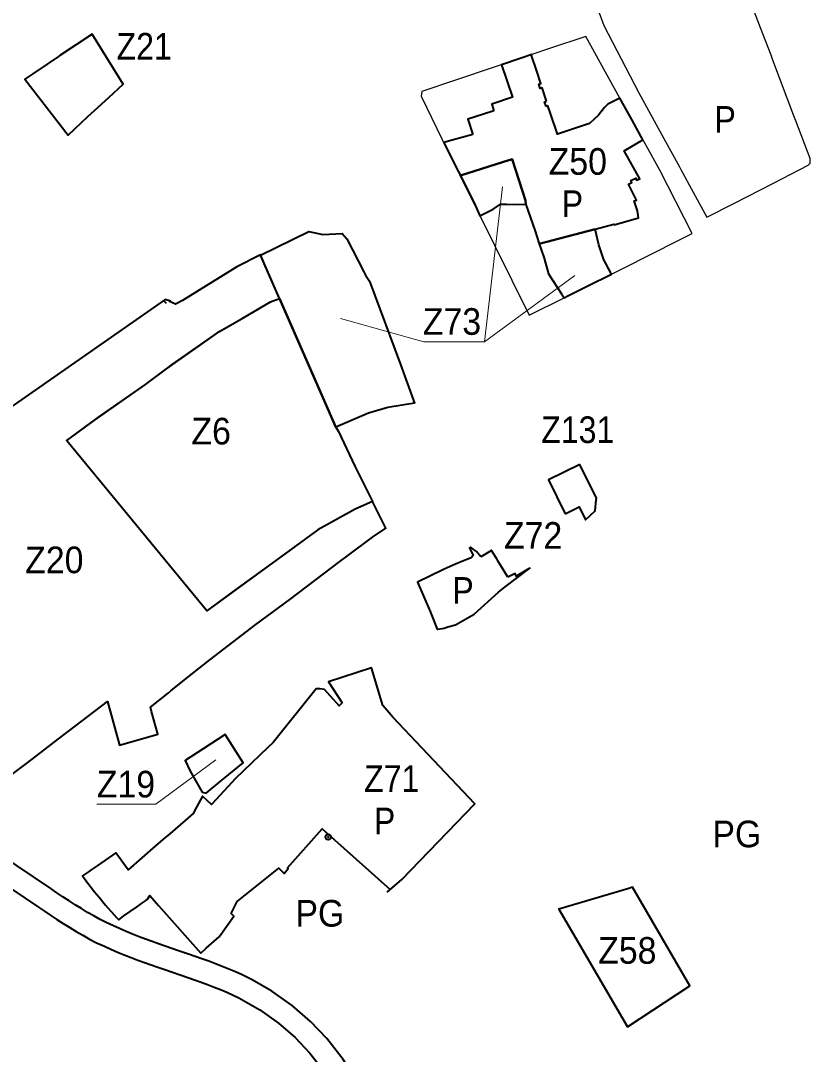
# Model space of a CAD drawing. Extents: x -650276 to -642489, y -1074311 to -1066658.
# Drawn here: x -648043 to -647332, y -1071620 to -1070690 of the extents above; entities that cross this region are included whole.
import ezdxf

# ---------------------------------------------------------------- set-up
doc = ezdxf.new("R2010")
doc.units = 0
doc.header["$LTSCALE"] = 9.6
doc.header["$PDMODE"] = 32
doc.header["$PDSIZE"] = 4.8
for name, color, linetype, lineweight in [('42', 7, 'Continuous', 25), ('44', 7, 'Continuous', 40), ('45', 7, 'Continuous', 40), ('46', 7, 'Continuous', 13), ('60', 7, 'Continuous', 35)]:
    doc.layers.add(name, color=color, linetype=linetype, lineweight=lineweight)

msp = doc.modelspace()

# ---------------------------------------------------------------- linework, layer by layer
at = {"layer": '42'}
for points in [[(-647523.27, -1070680.11), (-647518.19, -1070693.93), (-647502.59, -1070724.13), (-647486.84, -1070754.54), (-647464.3, -1070795.6), (-647450.23, -1070821.25), (-647448.84, -1070823.79), (-647437.79, -1070844.12), (-647425.58, -1070866.7), (-647401.15, -1070854.25), (-647365.48, -1070835.85), (-647334.27, -1070819.86), (-647332.51, -1070817.97), (-647332.25, -1070813.72), (-647345.18, -1070779.89), (-647346.96, -1070775.41), (-647365.94, -1070725.08), (-647367.67, -1070720.73), (-647377.04, -1070696.22), (-647386.39, -1070671.74)], [(-647717.363, -1071306.29), (-647727.368, -1071272.362), (-647766.35, -1071285.11), (-647753.89, -1071303.94), (-647756.67, -1071306.77), (-647769.85, -1071291.91), (-647774.14, -1071291.34), (-647777.4, -1071291.32), (-647815.95, -1071339.71), (-647820.93, -1071344.25), (-647849.86, -1071372.18), (-647867.45, -1071390.95), (-647871.68, -1071395.59), (-647879.76, -1071387.96), (-647885.05, -1071397.88), (-647888.11, -1071403.61), (-647895.29, -1071409.81), (-647904.3, -1071417.58), (-647911.04, -1071423.39), (-647913.31, -1071425.35), (-647921.96, -1071432.81), (-647946.78, -1071454.23), (-647957.906, -1071439.06), (-647974.66, -1071450.62), (-647977.28, -1071452.43), (-647979.88, -1071454.22), (-647982.46, -1071456), (-647985.06, -1071457.79), (-647987.8, -1071459.68), (-647984, -1071465), (-647977.13, -1071474.05), (-647972.76, -1071479)], [(-647710.546, -1071472.023), (-647700.078, -1071462.96), (-647634.524, -1071394.901), (-647708.429, -1071316.821), (-647717.363, -1071306.29)], [(-647803.1, -1071452.66), (-647771.82, -1071417.42), (-647710.546, -1071472.023)], [(-647848.4, -1071482.78), (-647810.97, -1071452.92), (-647806.15, -1071457.48)], [(-647806.15, -1071457.48), (-647802.53, -1071453.19), (-647803.1, -1071452.66)], [(-647972.76, -1071479), (-647967.13, -1071486.01), (-647957.07, -1071497.13), (-647955.14, -1071499.23), (-647950.56, -1071495.85), (-647944.81, -1071491.78), (-647939.31, -1071487.88), (-647933.88, -1071484.04), (-647931.17, -1071482.12), (-647929.26, -1071480.77), (-647927.2, -1071477.54), (-647919.22, -1071486.5), (-647881.16, -1071529.25)], [(-647881.16, -1071529.25), (-647876.27, -1071524.96), (-647864.69, -1071514.65), (-647851.45, -1071495.96), (-647853.77, -1071493.78), (-647848.4, -1071482.78)]]:
    msp.add_lwpolyline(points, dxfattribs=at)
msp.add_lwpolyline([(-647534.33, -1070703.84), (-647567.08, -1070714.8), (-647583.22, -1070720.2), (-647651.82, -1070743.17), (-647682.08, -1070753.29), (-647682.67, -1070757.67), (-647663.71, -1070796.77), (-647585.55, -1070954.94), (-647553.94, -1070939.11), (-647532.58, -1070928.392), (-647511.37, -1070917.79), (-647501.26, -1070912.72), (-647450.8, -1070887.42), (-647438.82, -1070881.43), (-647467.89, -1070824.15), (-647480.13, -1070802.09), (-647503.76, -1070759.31)], close=True, dxfattribs=at)
at = {"layer": '44'}
for points in [[(-647834.953, -1071553.406), (-647837.929, -1071551.872), (-647843.891, -1071549), (-647849.898, -1071546.282), (-647855.937, -1071543.707), (-647861.998, -1071541.254), (-647868.073, -1071538.911), (-647874.155, -1071536.658), (-647880.233, -1071534.48), (-647886.305, -1071532.36), (-647892.363, -1071530.282), (-647901.28, -1071527.249), (-647907.294, -1071525.204), (-647913.282, -1071523.152), (-647919.238, -1071521.081), (-647925.157, -1071518.976), (-647931.035, -1071516.824), (-647936.866, -1071514.613), (-647942.644, -1071512.329), (-647948.363, -1071509.96), (-647954.016, -1071507.496), (-647959.792, -1071504.833), (-647966.547, -1071501.883), (-647972.035, -1071499.009), (-647977.67, -1071495.885), (-647983.266, -1071492.628), (-647988.829, -1071489.259), (-647994.366, -1071485.79), (-647999.887, -1071482.241), (-648005.399, -1071478.627), (-648010.917, -1071474.963), (-648016.446, -1071471.268), (-648063.593, -1071439.723)], [(-648074.86, -1071456.248), (-648027.562, -1071487.894), (-648022.005, -1071491.607), (-648016.415, -1071495.321), (-648010.777, -1071499.017), (-648005.082, -1071502.678), (-647999.319, -1071506.287), (-647993.478, -1071509.826), (-647987.55, -1071513.275), (-647981.525, -1071516.615), (-647975.201, -1071519.929), (-647967.982, -1071523.081), (-647962.2, -1071525.746), (-647956.187, -1071528.368), (-647950.146, -1071530.869), (-647944.088, -1071533.263), (-647938.019, -1071535.566), (-647931.945, -1071537.788), (-647925.874, -1071539.949), (-647919.808, -1071542.058), (-647913.756, -1071544.132), (-647907.72, -1071546.185), (-647898.827, -1071549.208), (-647892.847, -1071551.26), (-647886.903, -1071553.336), (-647881.001, -1071555.45), (-647875.147, -1071557.619), (-647869.348, -1071559.856), (-647863.611, -1071562.177), (-647857.944, -1071564.594), (-647847.103, -1071569.497)], [(-647725.629, -1071678.373), (-647735.352, -1071657.117), (-647741.34, -1071644.028), (-647753.065, -1071625.201), (-647767.784, -1071606.225), (-647782.408, -1071590.847), (-647798.911, -1071576.526), (-647817.375, -1071563.458), (-647834.953, -1071553.406)], [(-647847.103, -1071569.497), (-647828.141, -1071580.34), (-647811.272, -1071592.28), (-647796.24, -1071605.324), (-647782.97, -1071619.278)], [(-647782.97, -1071619.278), (-647769.498, -1071636.647), (-647758.994, -1071653.513), (-647743.48, -1071687.426), (-647611.514, -1071974.086)]]:
    msp.add_lwpolyline(points, dxfattribs=at)
at = {"layer": '45'}
for p, q in [((-647914.73, -1070941.682), (-647912.347, -1070944.065)), ((-647914.73, -1070941.682), (-647912.347, -1070944.065)), ((-647713.442, -1071474.53), (-647700.078, -1071462.96)), ((-647713.442, -1071474.53), (-647700.078, -1071462.96))]:
    msp.add_line(p, q, dxfattribs=at)
for points in [[(-648032.601, -1070737.472), (-648039.82, -1070742.33), (-648000.85, -1070792.88), (-647994.63, -1070787.05), (-647982.89, -1070776.05), (-647976.97, -1070770.51), (-647964.21, -1070758.77), (-647951.11, -1070746.78), (-647979.17, -1070701.65), (-648008.28, -1070720.96), (-648009.29, -1070721.79), (-648019.49, -1070728.65)], [(-647827.363, -1070900.725), (-647783.95, -1070879.58), (-647771.47, -1070882.27), (-647753.81, -1070881.3), (-647749.75, -1070886.1), (-647734.48, -1070915.94), (-647732.97, -1070918.87), (-647729.27, -1070924.35), (-647701.45, -1070999.4), (-647688.9, -1071034.18), (-647712.74, -1071037.99), (-647730.17, -1071043.21), (-647759.52, -1071055.67)], [(-647827.363, -1070900.725), (-647783.95, -1070879.58), (-647771.47, -1070882.27), (-647753.81, -1070881.3), (-647749.75, -1070886.1), (-647734.48, -1070915.94), (-647732.97, -1070918.87), (-647729.27, -1070924.35), (-647701.45, -1070999.4), (-647688.9, -1071034.18), (-647712.74, -1071037.99), (-647730.17, -1071043.21), (-647759.52, -1071055.67)], [(-648001.766, -1071068.02), (-648001.922, -1071067.83), (-647973.304, -1071046.814), (-647930.96, -1071017.383), (-647912.11, -1071003.11), (-647906.9, -1070999.39), (-647875.248, -1070977.173), (-647864.03, -1070969.3), (-647843.928, -1070957.692), (-647818.33, -1070942.91), (-647810.243, -1070939.825), (-647759.52, -1071055.67), (-647757.19, -1071059.66), (-647742.64, -1071090.72), (-647726.74, -1071122.48), (-647742.35, -1071129.43), (-647775.982, -1071148.001), (-647775.982, -1071148.001), (-647875.939, -1071221.104)], [(-647974.66, -1071450.62), (-647977.28, -1071452.43), (-647979.88, -1071454.22), (-647982.46, -1071456), (-647985.06, -1071457.79), (-647987.8, -1071459.68), (-647984, -1071465), (-647977.13, -1071474.05), (-647972.76, -1071479), (-647967.13, -1071486.01), (-647957.07, -1071497.13), (-647955.14, -1071499.23), (-647950.56, -1071495.85), (-647944.81, -1071491.78), (-647939.31, -1071487.88), (-647933.88, -1071484.04), (-647931.17, -1071482.12), (-647929.26, -1071480.77), (-647927.2, -1071477.54), (-647919.22, -1071486.5), (-647881.16, -1071529.25), (-647876.27, -1071524.96), (-647864.69, -1071514.65), (-647851.45, -1071495.96), (-647853.77, -1071493.78), (-647848.4, -1071482.78), (-647810.97, -1071452.92), (-647806.15, -1071457.48), (-647802.53, -1071453.19), (-647803.1, -1071452.66), (-647771.82, -1071417.42), (-647710.546, -1071472.023), (-647700.078, -1071462.96), (-647634.524, -1071394.901), (-647708.429, -1071316.821), (-647717.363, -1071306.29), (-647727.368, -1071272.362), (-647766.35, -1071285.11), (-647753.89, -1071303.94), (-647756.67, -1071306.77), (-647769.85, -1071291.91), (-647774.14, -1071291.34), (-647777.4, -1071291.32), (-647815.95, -1071339.71), (-647820.93, -1071344.25), (-647849.86, -1071372.18), (-647867.45, -1071390.95), (-647871.68, -1071395.59), (-647879.76, -1071387.96), (-647885.05, -1071397.88), (-647888.11, -1071403.61), (-647895.29, -1071409.81), (-647904.3, -1071417.58), (-647911.04, -1071423.39), (-647913.31, -1071425.35), (-647921.96, -1071432.81), (-647946.78, -1071454.23), (-647957.906, -1071439.06)], [(-647974.66, -1071450.62), (-647977.28, -1071452.43), (-647979.88, -1071454.22), (-647982.46, -1071456), (-647985.06, -1071457.79), (-647987.8, -1071459.68), (-647984, -1071465), (-647977.13, -1071474.05), (-647972.76, -1071479), (-647967.13, -1071486.01), (-647957.07, -1071497.13), (-647955.14, -1071499.23), (-647950.56, -1071495.85), (-647944.81, -1071491.78), (-647939.31, -1071487.88), (-647933.88, -1071484.04), (-647931.17, -1071482.12), (-647929.26, -1071480.77), (-647927.2, -1071477.54), (-647919.22, -1071486.5), (-647881.16, -1071529.25), (-647876.27, -1071524.96), (-647864.69, -1071514.65), (-647851.45, -1071495.96), (-647853.77, -1071493.78), (-647848.4, -1071482.78), (-647810.97, -1071452.92), (-647806.15, -1071457.48), (-647802.53, -1071453.19), (-647803.1, -1071452.66), (-647771.82, -1071417.42), (-647710.546, -1071472.023), (-647700.078, -1071462.96), (-647634.524, -1071394.901), (-647708.429, -1071316.821), (-647717.363, -1071306.29), (-647727.368, -1071272.362), (-647766.35, -1071285.11), (-647753.89, -1071303.94), (-647756.67, -1071306.77), (-647769.85, -1071291.91), (-647774.14, -1071291.34), (-647777.4, -1071291.32), (-647815.95, -1071339.71), (-647820.93, -1071344.25), (-647849.86, -1071372.18), (-647867.45, -1071390.95), (-647871.68, -1071395.59), (-647879.76, -1071387.96), (-647885.05, -1071397.88), (-647888.11, -1071403.61), (-647895.29, -1071409.81), (-647904.3, -1071417.58), (-647911.04, -1071423.39), (-647913.31, -1071425.35), (-647921.96, -1071432.81), (-647946.78, -1071454.23), (-647957.906, -1071439.06)], [(-647879.09, -1071345.3), (-647895.37, -1071355.96), (-647890.7, -1071365.52), (-647880.14, -1071384.32), (-647876.34, -1071385.2), (-647862.25, -1071373.55), (-647859.44, -1071371.23), (-647843.23, -1071357.82), (-647859.31, -1071332.34)], [(-647879.09, -1071345.3), (-647895.37, -1071355.96), (-647890.7, -1071365.52), (-647880.14, -1071384.32), (-647876.34, -1071385.2), (-647862.25, -1071373.55), (-647859.44, -1071371.23), (-647843.23, -1071357.82), (-647859.31, -1071332.34)], [(-647497.04, -1071595.66), (-647440.67, -1071558.93), (-647492.3, -1071470), (-647495.85, -1071471.06), (-647558.654, -1071489.738)], [(-647497.04, -1071595.66), (-647440.67, -1071558.93), (-647492.3, -1071470), (-647495.85, -1071471.06), (-647558.654, -1071489.738)]]:
    msp.add_lwpolyline(points, close=True, dxfattribs=at)
for points in [[(-647569.92, -1070762.24), (-647573.88, -1070750.25), (-647575.58, -1070750.83), (-647576.81, -1070746.86), (-647575.09, -1070746.33), (-647578.79, -1070734.33), (-647583.38, -1070720.9), (-647583.22, -1070720.2), (-647593.6, -1070723.68), (-647610.33, -1070729.28), (-647600.53, -1070758.65), (-647619.2, -1070764.85), (-647617.36, -1070770.69)], [(-647636.12, -1070792.13), (-647654.89, -1070797.23), (-647662.26, -1070799.23), (-647650.908, -1070822.34), (-647647.405, -1070829.08), (-647609.58, -1070817.06), (-647600.8, -1070814.27), (-647588.89, -1070851.67), (-647588.4, -1070855.25), (-647584.6, -1070866.3), (-647580.22, -1070879.3), (-647578.703, -1070883.851), (-647578.703, -1070883.851), (-647576.469, -1070890.564), (-647526.13, -1070877.41), (-647509.1, -1070872.96), (-647508.96, -1070873.41), (-647487.16, -1070867.32), (-647487.91, -1070860.91), (-647490.92, -1070851.82), (-647488.8, -1070851.12), (-647494.1, -1070840.58), (-647495.93, -1070836.86), (-647493.16, -1070835.5), (-647494.03, -1070833.64), (-647489.55, -1070831.53), (-647488.75, -1070833.37), (-647485.9, -1070832), (-647500.07, -1070806.87), (-647500.07, -1070806.87), (-647483.16, -1070797.07), (-647492.81, -1070779.18), (-647492.81, -1070779.18), (-647497.227, -1070771.165), (-647503.76, -1070759.31), (-647514.49, -1070764.93), (-647517.61, -1070767.89), (-647523.07, -1070774.86), (-647531.05, -1070782.23), (-647560.06, -1070791.72), (-647566.26, -1070773.148)], [(-647570.27, -1070766.86), (-647571.63, -1070762.82), (-647569.92, -1070762.24)], [(-647617.36, -1070770.69), (-647619.12, -1070771.28), (-647640.66, -1070778.47), (-647636.12, -1070792.13)], [(-647566.26, -1070773.148), (-647568.55, -1070766.29), (-647570.27, -1070766.86)], [(-647588.4, -1070855.25), (-647588.89, -1070851.67), (-647600.8, -1070814.27), (-647609.58, -1070817.06), (-647647.405, -1070829.08)], [(-647588.4, -1070855.25), (-647588.89, -1070851.67), (-647600.8, -1070814.27), (-647609.58, -1070817.06), (-647647.405, -1070829.08)], [(-647647.405, -1070829.08), (-647635.11, -1070853.786), (-647629.92, -1070865.35), (-647618.01, -1070859.42), (-647611.3, -1070854.9), (-647605.64, -1070854.99), (-647588.4, -1070855.25)], [(-647647.405, -1070829.08), (-647635.11, -1070853.786), (-647629.92, -1070865.35), (-647618.01, -1070859.42), (-647611.3, -1070854.9), (-647605.64, -1070854.99), (-647588.4, -1070855.25)], [(-647511.37, -1070917.79), (-647516.66, -1070907.8), (-647518.12, -1070905.05), (-647522.74, -1070891.48), (-647526.13, -1070877.41), (-647576.469, -1070890.564)], [(-647576.469, -1070890.564), (-647576.43, -1070890.68), (-647572.32, -1070902.72), (-647568.2, -1070917.54), (-647556.52, -1070935.59), (-647553.94, -1070939.11)], [(-648060.01, -1071374.69), (-648038.18, -1071358.51), (-648025.39, -1071348.76), (-648009.31, -1071336.48), (-647994.31, -1071325.03), (-647965.26, -1071302.86), (-647954.38, -1071342), (-647919.88, -1071332.23), (-647925.6, -1071311.69), (-647926.69, -1071307.81), (-647910.73, -1071295.08), (-647907.92, -1071292.84), (-647888.77, -1071277.56), (-647873.25, -1071265.17), (-647831.565, -1071233.455), (-647801.178, -1071210.742), (-647756.03, -1071176.76), (-647750.34, -1071172.5), (-647726.56, -1071154.68), (-647714.71, -1071146.51), (-647714.71, -1071146.51), (-647719.73, -1071136.48), (-647726.74, -1071122.48), (-647742.35, -1071129.43), (-647775.982, -1071148.001), (-647808.402, -1071171.711), (-647848.51, -1071201.045), (-647875.939, -1071221.104), (-648001.766, -1071068.02), (-648001.922, -1071067.83), (-647977.41, -1071049.74), (-647930.96, -1071017.383), (-647911.838, -1071002.919), (-647912.11, -1071003.11), (-647864.29, -1070969.503), (-647838.842, -1070954.778), (-647818.33, -1070942.91), (-647810.243, -1070939.825), (-647827.527, -1070900.351), (-647848.89, -1070911.21), (-647897.76, -1070941.62), (-647904.13, -1070944.78), (-647909.42, -1070942.63), (-647908.63, -1070942.1), (-647913.45, -1070940.79), (-648062.53, -1071044.59)], [(-647553.94, -1070939.11), (-647553.94, -1070939.11), (-647550.59, -1070937.45), (-647533.31, -1070928.79), (-647511.37, -1070917.79)], [(-647539.818, -1071089.2), (-647568.01, -1071102.98), (-647553.01, -1071133.68)], [(-647525.1, -1071121.25), (-647524.95, -1071119.68), (-647539.817, -1071089.199)], [(-647553.01, -1071133.68), (-647540.48, -1071127.55), (-647534.851, -1071139.015), (-647526.04, -1071130.94), (-647525.1, -1071121.25)], [(-647629.09, -1071172.4), (-647632.93, -1071167.71), (-647638.46, -1071163.89), (-647639.32, -1071164.22), (-647635.93, -1071171.22)], [(-647629.09, -1071172.4), (-647632.93, -1071167.71), (-647638.46, -1071163.89), (-647639.32, -1071164.22), (-647635.93, -1071171.22)], [(-647635.93, -1071171.22), (-647637.87, -1071173.29), (-647646.09, -1071176.68), (-647653.85, -1071179.87), (-647662.634, -1071183.968)], [(-647635.93, -1071171.22), (-647637.87, -1071173.29), (-647646.09, -1071176.68), (-647653.85, -1071179.87), (-647662.634, -1071183.968)], [(-647612.695, -1071177.542), (-647613.91, -1071175.57), (-647614.732, -1071174.222), (-647618.446, -1071168.166), (-647618.469, -1071168.129), (-647618.77, -1071167.64), (-647619.264, -1071166.832), (-647619.34, -1071166.709), (-647628.39, -1071172.05), (-647629.09, -1071172.4)], [(-647612.695, -1071177.542), (-647613.91, -1071175.57), (-647614.732, -1071174.222), (-647618.446, -1071168.166), (-647618.469, -1071168.129), (-647618.77, -1071167.64), (-647619.264, -1071166.832), (-647619.34, -1071166.709), (-647628.39, -1071172.05), (-647629.09, -1071172.4)], [(-647662.634, -1071183.968), (-647686.01, -1071195.35), (-647686.01, -1071195.35)], [(-647662.634, -1071183.968), (-647686.01, -1071195.35), (-647686.01, -1071195.35)], [(-647674.6, -1071221.71), (-647668.226, -1071237.571), (-647667.77, -1071237.5), (-647661.99, -1071236.62), (-647658.78, -1071235.63), (-647651.93, -1071233.57), (-647635.17, -1071224.18), (-647613.09, -1071204.33), (-647607.02, -1071199.34), (-647584.92, -1071182.54), (-647597.164, -1071189.857), (-647598.215, -1071187.608), (-647604.576, -1071190.781)], [(-647674.6, -1071221.71), (-647668.226, -1071237.571), (-647667.77, -1071237.5), (-647661.99, -1071236.62), (-647658.78, -1071235.63), (-647651.93, -1071233.57), (-647635.17, -1071224.18), (-647613.09, -1071204.33), (-647607.02, -1071199.34), (-647584.92, -1071182.54), (-647597.164, -1071189.857), (-647598.215, -1071187.608), (-647604.576, -1071190.781)], [(-647604.576, -1071190.781), (-647604.888, -1071190.272), (-647612.695, -1071177.542)], [(-647604.576, -1071190.781), (-647604.888, -1071190.272), (-647612.695, -1071177.542)], [(-647686.01, -1071195.35), (-647686.01, -1071195.35), (-647674.6, -1071221.71)], [(-647686.01, -1071195.35), (-647686.01, -1071195.35), (-647674.6, -1071221.71)]]:
    msp.add_lwpolyline(points, dxfattribs=at)
msp.add_point((-647766.557, -1071424.793), dxfattribs=at)
at = {"layer": '46'}
for points in [[(-647544.337, -1070919.163), (-647625.809, -1070978.773), (-647609.46, -1070839.305), (-647625.809, -1070978.773), (-647680.348, -1070978.773), (-647755.299, -1070957.715)], [(-647544.337, -1070919.163), (-647625.809, -1070978.773), (-647609.46, -1070839.305), (-647625.809, -1070978.773), (-647680.348, -1070978.773), (-647755.299, -1070957.715)], [(-647974.97, -1071395.111), (-647921.786, -1071395.111), (-647867.57, -1071355.322)], [(-647974.97, -1071395.111), (-647921.786, -1071395.111), (-647867.57, -1071355.322)]]:
    msp.add_lwpolyline(points, dxfattribs=at)

# ---------------------------------------------------------------- texts
for s, width, p in [('Z21', 0.9, (-647957.11, -1070724.677)), ('Z50', 0.95, (-647567.967, -1070828.405)), ('Z50', 0.95, (-647567.967, -1070828.405)), ('Z73', 0.95, (-647681.324, -1070972.53)), ('Z73', 0.95, (-647681.324, -1070972.53)), ('Z6', 0.95, (-647889.738, -1071071.271)), ('Z131', 0.9, (-647574.644, -1071069.985)), ('Z72', 0.95, (-647608.212, -1071165.192)), ('Z72', 0.95, (-647608.212, -1071165.192)), ('Z20', 0.95, (-648039.444, -1071187.201)), ('Z71', 0.9, (-647734.152, -1071384.125)), ('Z71', 0.9, (-647734.152, -1071384.125)), ('Z19', 0.95, (-647974.958, -1071389.14)), ('Z19', 0.95, (-647974.958, -1071389.14)), ('Z58', 0.95, (-647523.363, -1071538.888)), ('Z58', 0.95, (-647523.363, -1071538.888))]:
    msp.add_text(s, height=24, dxfattribs=dict(at, width=width)).set_placement(p)
at = {"layer": '60'}
for s, width, p in [('P', 0.9, (-647418.572, -1070790.564)), ('P', 0.9, (-647418.572, -1070790.564)), ('P', 0.9, (-647556.162, -1070866.47)), ('P', 0.9, (-647556.162, -1070866.47)), ('P', 0.9, (-647654.706, -1071214.743)), ('P', 0.9, (-647654.706, -1071214.743)), ('P', 0.9, (-647725.36, -1071422.368)), ('P', 0.9, (-647725.36, -1071422.368)), ('PG', 0.95, (-647420.449, -1071434.013)), ('PG', 0.95, (-647420.449, -1071434.013)), ('PG', 0.95, (-647796.031, -1071505.454)), ('PG', 0.95, (-647796.031, -1071505.454))]:
    msp.add_text(s, height=24, dxfattribs=dict(at, width=width)).set_placement(p)

doc.saveas('drawing.dxf')
